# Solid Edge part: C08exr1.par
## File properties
Author: TIET
Template: iso metric part.par
Last saved by: TIET
Revision: 1
Application: Solid Edge
Accuracy: 0.990
Username: TIET
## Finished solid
Body 1: solid body, 34 faces, 81 edges, 46 vertices.
  Faces by surface: plane 28, cylinder 6
  Edges by curve: line 67, circle 14
Bounding box of the edges (mm): 92.000 x 170.000 x 106.000, from (-46, -30, -30) to (46, 140, 76).
Cylindrical faces by radius (mm): R8 x2, R16 x2, R18 x1, R30 x1
Planar faces by outward normal: +x 5, +y 3, +z 4, -x 5, -y 5, -z 4, oblique 2
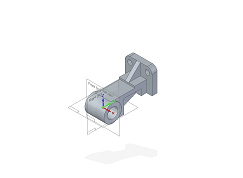
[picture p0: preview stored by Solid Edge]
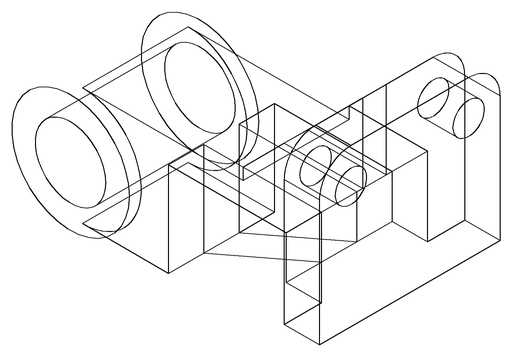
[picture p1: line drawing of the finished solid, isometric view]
